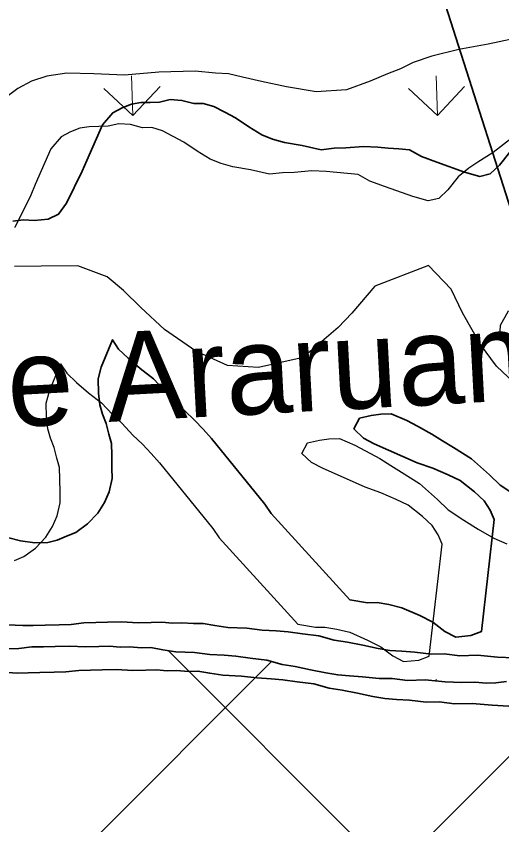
# Model space of a CAD drawing. Extents: x -10.5 to 30.8, y 18.4 to 58.7.
# Drawn here: x 1.997 to 3.031, y 33.091 to 34.811 of the extents above; entities that cross this region are included whole.
import ezdxf

# ---------------------------------------------------------------- set-up
doc = ezdxf.new("R2010")
doc.units = 0
doc.header["$LTSCALE"] = 0.08
for name, color, linetype, lineweight in [('10', 7, 'Continuous', 35), ('11', 7, 'Continuous', 13), ('18', 7, 'Continuous', 25), ('21', 7, 'Continuous', 25), ('43', 7, 'Continuous', 13), ('47', 7, 'Continuous', 25), ('48', 7, 'Continuous', 35), ('50', 7, 'Continuous', 25), ('51', 7, 'Continuous', 35), ('9', 7, 'Continuous', 25)]:
    doc.layers.add(name, color=color, linetype=linetype, lineweight=lineweight)

msp = doc.modelspace()

# ---------------------------------------------------------------- linework, layer by layer
at = {"layer": '10'}
for points in [[(2.9101, 33.39517), (2.86736, 33.39914), (2.82976, 33.39824), (2.79705, 33.40247), (2.76947, 33.4018), (2.73425, 33.40597), (2.70662, 33.4078), (2.68149, 33.4097), (2.6563, 33.41411), (2.62353, 33.42083), (2.59077, 33.42755), (2.56307, 33.43189), (2.53025, 33.44112), (2.49503, 33.44528), (2.46482, 33.44956), (2.43969, 33.45146), (2.40956, 33.45324), (2.37684, 33.45746), (2.33667, 33.459), (2.30898, 33.46335), (2.28379, 33.46775), (2.26372, 33.46727), (2.23859, 33.46916), (2.21854, 33.46869), (2.19592, 33.47064), (2.17335, 33.4701), (2.14578, 33.46944), (2.11062, 33.4711), (2.08054, 33.47038), (2.05546, 33.46978), (2.03039, 33.46918), (2.00286, 33.46602), (1.97779, 33.46541)], [(3.04054, 33.39579), (3.01803, 33.39275), (2.99797, 33.39227), (2.97284, 33.39417), (2.94527, 33.39351), (2.9101, 33.39517)]]:
    msp.add_lwpolyline(points, dxfattribs=at)
at = {"layer": '11'}
msp.add_lwpolyline([(1.99392, 34.27854), (2.05029, 34.27957), (2.12812, 34.27988), (2.19108, 34.25681), (2.22558, 34.22765), (2.2623, 34.19109), (2.31268, 34.14481), (2.37966, 34.09819), (2.44718, 34.06804), (2.51297, 34.0639), (2.60779, 34.08497), (2.6826, 34.14912), (2.7117, 34.17907), (2.76039, 34.23687), (2.87477, 34.28096), (2.92274, 34.2301), (2.94717, 34.17973), (2.98527, 34.11266), (3.01942, 34.06686), (3.10428, 33.98663)], dxfattribs=at)
at = {"layer": '18'}
msp.add_lwpolyline([(3.10428, 33.98663), (3.01942, 34.06686), (2.98527, 34.11266), (2.94717, 34.17973), (2.92274, 34.2301), (2.87477, 34.28096), (2.76039, 34.23687), (2.7117, 34.17907), (2.6826, 34.14912), (2.60779, 34.08497), (2.51297, 34.0639), (2.44718, 34.06804), (2.37966, 34.09819), (2.31268, 34.14481), (2.2623, 34.19109), (2.22558, 34.22765), (2.19108, 34.25681), (2.12812, 34.27988), (2.05029, 34.27957), (1.99392, 34.27854)], dxfattribs=at)
at = {"layer": '21'}
for p, q in [((3.73639, 32.04564), (2.32048, 33.46154)), ((0.73047, 31.62819), (2.54052, 33.43823)), ((1.49157, 31.68218), (3.22205, 33.41266))]:
    msp.add_line(p, q, dxfattribs=at)
for points in [[(2.9101, 33.39517), (2.86736, 33.39914), (2.82976, 33.39824), (2.79705, 33.40247), (2.76947, 33.4018), (2.73425, 33.40597), (2.70662, 33.4078), (2.68149, 33.4097), (2.6563, 33.41411), (2.62353, 33.42083), (2.59077, 33.42755), (2.56307, 33.43189), (2.53025, 33.44112), (2.49503, 33.44528), (2.46482, 33.44956), (2.43969, 33.45146), (2.40956, 33.45324), (2.37684, 33.45746), (2.33667, 33.459), (2.30898, 33.46335), (2.28379, 33.46775), (2.26372, 33.46727), (2.23859, 33.46916), (2.21854, 33.46869), (2.19592, 33.47064), (2.17335, 33.4701), (2.14578, 33.46944), (2.11062, 33.4711), (2.08054, 33.47038), (2.05546, 33.46978), (2.03039, 33.46918), (2.00286, 33.46602), (1.97779, 33.46541)], [(3.04054, 33.39579), (3.01803, 33.39275), (2.99797, 33.39227), (2.97284, 33.39417), (2.94527, 33.39351), (2.9101, 33.39517)]]:
    msp.add_lwpolyline(points, dxfattribs=at)
at = {"layer": '43'}
for p, q in [((2.24562, 34.59965), (2.24282, 34.68398)), ((2.24562, 34.59965), (2.24282, 34.68398)), ((2.89348, 34.59965), (2.89067, 34.68398)), ((2.89348, 34.59965), (2.89067, 34.68398)), ((2.24562, 34.59965), (2.18401, 34.6573)), ((2.24562, 34.59965), (2.18401, 34.6573)), ((2.24562, 34.59965), (2.30327, 34.66127)), ((2.24562, 34.59965), (2.30327, 34.66127)), ((2.89348, 34.59965), (2.83186, 34.6573)), ((2.89348, 34.59965), (2.83186, 34.6573)), ((2.89348, 34.59965), (2.95112, 34.66127)), ((2.89348, 34.59965), (2.95112, 34.66127)), ((2.89079, 33.39696), (2.89067, 33.40042)), ((2.89079, 33.39696), (2.89067, 33.40042))]:
    msp.add_line(p, q, dxfattribs=at)
for points in [[(3.05641, 34.55508), (3.01203, 34.52148), (2.97989, 34.50068), (2.96013, 34.48769), (2.93796, 34.46964), (2.91604, 34.44158), (2.89638, 34.42359), (2.87394, 34.41804), (2.84111, 34.42727), (2.78292, 34.4484), (2.75003, 34.46012), (2.72462, 34.47454), (2.702, 34.47649), (2.67937, 34.47846), (2.65676, 34.48042), (2.62661, 34.4822), (2.58906, 34.47879), (2.56399, 34.47819), (2.53647, 34.47503), (2.49612, 34.48407), (2.45834, 34.49067), (2.43309, 34.49758), (2.41029, 34.50704), (2.38232, 34.5239), (2.35427, 34.54324), (2.33142, 34.55521), (2.30857, 34.56718), (2.28583, 34.57414), (2.26577, 34.57366), (2.24053, 34.58057), (2.2154, 34.58247), (2.19294, 34.57692), (2.17289, 34.57644), (2.15283, 34.57596), (2.13283, 34.57298), (2.11294, 34.56499), (2.09312, 34.5545), (2.07113, 34.52895), (2.03776, 34.45305), (2.02825, 34.4303), (1.99471, 34.36191)], [(3.05641, 34.55508), (3.01203, 34.52148), (2.97989, 34.50068), (2.96013, 34.48769), (2.93796, 34.46964), (2.91604, 34.44158), (2.89638, 34.42359), (2.87394, 34.41804), (2.84111, 34.42727), (2.78292, 34.4484), (2.75003, 34.46012), (2.72462, 34.47454), (2.702, 34.47649), (2.67937, 34.47846), (2.65676, 34.48042), (2.62661, 34.4822), (2.58906, 34.47879), (2.56399, 34.47819), (2.53647, 34.47503), (2.49612, 34.48407), (2.45834, 34.49067), (2.43309, 34.49758), (2.41029, 34.50704), (2.38232, 34.5239), (2.35427, 34.54324), (2.33142, 34.55521), (2.30857, 34.56718), (2.28583, 34.57414), (2.26577, 34.57366), (2.24053, 34.58057), (2.2154, 34.58247), (2.19294, 34.57692), (2.17289, 34.57644), (2.15283, 34.57596), (2.13283, 34.57298), (2.11294, 34.56499), (2.09312, 34.5545), (2.07113, 34.52895), (2.03776, 34.45305), (2.02825, 34.4303), (1.99471, 34.36191)], [(3.04623, 34.12682), (3.02617, 34.12634), (3.02805, 34.15391), (3.0449, 34.18435)], [(3.04623, 34.12682), (3.02617, 34.12634), (3.02805, 34.15391), (3.0449, 34.18435)], [(1.99351, 33.65352), (2.0134, 33.6615), (2.03807, 33.67962), (2.06011, 33.70267), (2.07464, 33.72555), (2.08414, 33.7483), (2.09103, 33.77601), (2.09052, 33.79852), (2.08987, 33.82604), (2.0893, 33.85106), (2.08383, 33.87095), (2.07828, 33.89334), (2.07031, 33.91318), (2.06483, 33.93307), (2.06174, 33.95803), (2.06104, 33.98805), (2.06799, 34.01324), (2.09173, 34.07138), (2.10473, 34.05167), (2.12525, 34.03214), (2.15084, 34.01022), (2.17894, 33.98837), (2.20208, 33.96389), (2.2226, 33.94436), (2.24576, 33.91989), (2.26627, 33.90036), (2.28428, 33.88076), (2.30229, 33.86117), (2.4159, 33.72122), (2.4289, 33.70151), (2.5962, 33.51779), (2.63398, 33.51119), (2.65404, 33.51167), (2.67923, 33.50727), (2.70699, 33.50043), (2.745, 33.48382), (2.77293, 33.46947), (2.79846, 33.45006), (2.82132, 33.43809), (2.85385, 33.44137), (2.87624, 33.44942), (2.90334, 33.68786), (2.89536, 33.70769), (2.88236, 33.72741), (2.86184, 33.74694), (2.83118, 33.77123), (2.80582, 33.78314), (2.77287, 33.79737), (2.73999, 33.80909), (2.64875, 33.84946), (2.6259, 33.86142), (2.60538, 33.88096), (2.61739, 33.90377), (2.64235, 33.90938), (2.66235, 33.91236), (2.68492, 33.9129), (2.71785, 33.89867), (2.74071, 33.8867), (2.7712, 33.86992), (2.79411, 33.85545), (2.81703, 33.84098), (2.85521, 33.81686), (2.89362, 33.78274), (2.91671, 33.76077), (2.94983, 33.73903), (2.98037, 33.71974), (3.01344, 33.70051), (3.0413, 33.68866)], [(1.99351, 33.65352), (2.0134, 33.6615), (2.03807, 33.67962), (2.06011, 33.70267), (2.07464, 33.72555), (2.08414, 33.7483), (2.09103, 33.77601), (2.09052, 33.79852), (2.08987, 33.82604), (2.0893, 33.85106), (2.08383, 33.87095), (2.07828, 33.89334), (2.07031, 33.91318), (2.06483, 33.93307), (2.06174, 33.95803), (2.06104, 33.98805), (2.06799, 34.01324), (2.09173, 34.07138), (2.10473, 34.05167), (2.12525, 34.03214), (2.15084, 34.01022), (2.17894, 33.98837), (2.20208, 33.96389), (2.2226, 33.94436), (2.24576, 33.91989), (2.26627, 33.90036), (2.28428, 33.88076), (2.30229, 33.86117), (2.4159, 33.72122), (2.4289, 33.70151), (2.5962, 33.51779), (2.63398, 33.51119), (2.65404, 33.51167), (2.67923, 33.50727), (2.70699, 33.50043), (2.745, 33.48382), (2.77293, 33.46947), (2.79846, 33.45006), (2.82132, 33.43809), (2.85385, 33.44137), (2.87624, 33.44942), (2.90334, 33.68786), (2.89536, 33.70769), (2.88236, 33.72741), (2.86184, 33.74694), (2.83118, 33.77123), (2.80582, 33.78314), (2.77287, 33.79737), (2.73999, 33.80909), (2.64875, 33.84946), (2.6259, 33.86142), (2.60538, 33.88096), (2.61739, 33.90377), (2.64235, 33.90938), (2.66235, 33.91236), (2.68492, 33.9129), (2.71785, 33.89867), (2.74071, 33.8867), (2.7712, 33.86992), (2.79411, 33.85545), (2.81703, 33.84098), (2.85521, 33.81686), (2.89362, 33.78274), (2.91671, 33.76077), (2.94983, 33.73903), (2.98037, 33.71974), (3.01344, 33.70051), (3.0413, 33.68866)], [(1.97779, 33.46541), (2.00286, 33.46602), (2.03039, 33.46918), (2.05546, 33.46978), (2.08054, 33.47038), (2.11062, 33.4711), (2.14578, 33.46944), (2.17335, 33.4701), (2.19592, 33.47064), (2.21854, 33.46869), (2.23859, 33.46916), (2.26372, 33.46727), (2.28379, 33.46775), (2.30898, 33.46335), (2.33667, 33.459), (2.37684, 33.45746), (2.40956, 33.45324), (2.43969, 33.45146), (2.46482, 33.44956), (2.49503, 33.44528), (2.53025, 33.44112), (2.56307, 33.43189), (2.59077, 33.42755), (2.62353, 33.42083), (2.6563, 33.41411), (2.68149, 33.4097), (2.70662, 33.4078), (2.73425, 33.40597), (2.76947, 33.4018), (2.79705, 33.40247), (2.82976, 33.39824), (2.86736, 33.39914), (2.9101, 33.39517)], [(1.97779, 33.46541), (2.00286, 33.46602), (2.03039, 33.46918), (2.05546, 33.46978), (2.08054, 33.47038), (2.11062, 33.4711), (2.14578, 33.46944), (2.17335, 33.4701), (2.19592, 33.47064), (2.21854, 33.46869), (2.23859, 33.46916), (2.26372, 33.46727), (2.28379, 33.46775), (2.30898, 33.46335), (2.33667, 33.459), (2.37684, 33.45746), (2.40956, 33.45324), (2.43969, 33.45146), (2.46482, 33.44956), (2.49503, 33.44528), (2.53025, 33.44112), (2.56307, 33.43189), (2.59077, 33.42755), (2.62353, 33.42083), (2.6563, 33.41411), (2.68149, 33.4097), (2.70662, 33.4078), (2.73425, 33.40597), (2.76947, 33.4018), (2.79705, 33.40247), (2.82976, 33.39824), (2.86736, 33.39914), (2.9101, 33.39517)], [(2.9101, 33.39517), (2.94527, 33.39351), (2.97284, 33.39417), (2.99797, 33.39227), (3.01803, 33.39275), (3.04054, 33.39579)], [(2.9101, 33.39517), (2.94527, 33.39351), (2.97284, 33.39417), (2.99797, 33.39227), (3.01803, 33.39275), (3.04054, 33.39579)]]:
    msp.add_lwpolyline(points, dxfattribs=at)
at = {"layer": '48'}
for points in [[(1.99008, 34.37516), (2.01258, 34.37823), (2.03521, 34.3763), (2.06523, 34.37957), (2.08755, 34.39015), (2.10454, 34.41311), (2.13799, 34.48154), (2.14747, 34.50431), (2.18073, 34.58025), (2.20269, 34.60583), (2.22249, 34.61635), (2.24237, 34.62436), (2.26237, 34.62737), (2.28243, 34.62788), (2.30248, 34.62839), (2.32493, 34.63396), (2.35006, 34.6321), (2.37531, 34.62523), (2.39537, 34.62574), (2.41812, 34.61881), (2.44099, 34.60687), (2.46385, 34.59493), (2.49193, 34.57562), (2.51993, 34.55881), (2.54274, 34.54938), (2.568, 34.54251), (2.60579, 34.53595), (2.64614, 34.52697), (2.67366, 34.53017), (2.69873, 34.5308), (2.73627, 34.53426), (2.76643, 34.53252), (2.78904, 34.53059), (2.81167, 34.52866), (2.8343, 34.52673), (2.85973, 34.51236), (2.89263, 34.50068), (2.95086, 34.47963), (2.98369, 34.47045), (3.00613, 34.47602), (3.02576, 34.49404), (3.04764, 34.52213)], [(3.06052, 33.79154), (3.02737, 33.81323), (3.00425, 33.83517), (2.96579, 33.86924), (2.92757, 33.8933), (2.90463, 33.90774), (2.88171, 33.92218), (2.85119, 33.93892), (2.82832, 33.95086), (2.79537, 33.96504), (2.7728, 33.96447), (2.7528, 33.96146), (2.72785, 33.95582), (2.71587, 33.93299), (2.73642, 33.91349), (2.75928, 33.90155), (2.85058, 33.86131), (2.88348, 33.84963), (2.91644, 33.83545), (2.94182, 33.82357), (2.97251, 33.79932), (2.99307, 33.77982), (3.00609, 33.76012), (3.0141, 33.7403), (2.98733, 33.50183), (2.96494, 33.49375), (2.93242, 33.49042), (2.90954, 33.50235), (2.88398, 33.52173), (2.85604, 33.53604), (2.818, 33.5526), (2.79024, 33.55941), (2.76504, 33.56377), (2.74498, 33.56326), (2.70719, 33.56981), (2.53964, 33.7533), (2.52661, 33.77299), (2.41281, 33.91278), (2.39477, 33.93236), (2.37674, 33.95192), (2.35619, 33.97143), (2.33301, 33.99587), (2.31246, 34.01537), (2.28928, 34.03982), (2.26116, 34.06163), (2.23553, 34.08351), (2.21499, 34.10302), (2.20196, 34.12271), (2.1783, 34.06454), (2.17139, 34.03933), (2.17213, 34.00931), (2.17525, 33.98436), (2.18076, 33.96448), (2.18876, 33.94465), (2.19433, 33.92227), (2.19983, 33.90238), (2.20044, 33.87736), (2.20112, 33.84985), (2.20167, 33.82733), (2.19482, 33.79962), (2.18535, 33.77686), (2.17085, 33.75396), (2.14884, 33.73087), (2.1242, 33.71273), (2.10432, 33.70471), (2.08445, 33.6967), (2.06452, 33.69119), (2.03693, 33.69049), (2.00673, 33.69473), (1.98147, 33.7016)], [(1.97848, 33.51629), (2.01114, 33.51462), (2.0337, 33.51519), (2.05878, 33.51582), (2.08886, 33.51659), (2.11393, 33.51722), (2.14145, 33.52042), (2.16652, 33.52106), (2.19159, 33.5217), (2.22168, 33.52246), (2.25684, 33.52085), (2.28441, 33.52155), (2.30698, 33.52212), (2.32961, 33.52019), (2.34966, 33.5207), (2.37479, 33.51883), (2.39485, 33.51934), (2.42004, 33.51498), (2.44775, 33.51067), (2.48792, 33.50919), (2.52064, 33.50501), (2.55078, 33.50327), (2.57591, 33.50141), (2.60612, 33.49717), (2.64134, 33.49305), (2.67419, 33.48387), (2.70188, 33.47957), (2.73466, 33.47289), (2.76743, 33.46621), (2.79263, 33.46185), (2.81776, 33.45998), (2.84541, 33.45818), (2.88062, 33.45406), (2.9082, 33.45476), (2.94092, 33.45059), (2.97852, 33.45154), (3.02127, 33.44762), (3.05643, 33.44601)], [(3.05643, 33.44601), (3.02127, 33.44762), (2.97852, 33.45154), (2.94092, 33.45059), (2.9082, 33.45476), (2.88062, 33.45406), (2.84541, 33.45818), (2.81776, 33.45998), (2.79263, 33.46185), (2.76743, 33.46621), (2.73466, 33.47289), (2.70188, 33.47957), (2.67419, 33.48387), (2.64134, 33.49305), (2.60612, 33.49717), (2.57591, 33.50141), (2.55078, 33.50327), (2.52064, 33.50501), (2.48792, 33.50919), (2.44775, 33.51067), (2.42004, 33.51498), (2.39485, 33.51934), (2.37479, 33.51883), (2.34966, 33.5207), (2.32961, 33.52019), (2.30698, 33.52212), (2.28441, 33.52155), (2.25684, 33.52085), (2.22168, 33.52246), (2.19159, 33.5217), (2.16652, 33.52106), (2.14145, 33.52042), (2.11393, 33.51722), (2.08886, 33.51659), (2.05878, 33.51582), (2.0337, 33.51519), (2.01114, 33.51462), (1.97848, 33.51629)], [(1.96742, 33.41527), (2.00007, 33.41355), (2.02264, 33.41409), (2.04771, 33.41469), (2.07779, 33.41541), (2.10286, 33.41602), (2.13039, 33.41918), (2.15546, 33.41978), (2.18054, 33.42038), (2.21062, 33.4211), (2.24578, 33.41944), (2.27335, 33.4201), (2.29592, 33.42064), (2.31854, 33.41869), (2.33859, 33.41916), (2.36372, 33.41727), (2.38379, 33.41775), (2.40898, 33.41335), (2.43667, 33.409), (2.47684, 33.40746), (2.50956, 33.40324), (2.53969, 33.40146), (2.56482, 33.39956), (2.59503, 33.39528)], [(2.59503, 33.39528), (2.63025, 33.39112), (2.66307, 33.38189), (2.69077, 33.37755), (2.72353, 33.37083), (2.7563, 33.36411), (2.78149, 33.3597), (2.80662, 33.3578), (2.83425, 33.35596), (2.86947, 33.3518), (2.89705, 33.35247), (2.92976, 33.34824), (2.96736, 33.34914), (3.0101, 33.34517)], [(3.0101, 33.34517), (3.04527, 33.34351)]]:
    msp.add_lwpolyline(points, dxfattribs=at)
at = {"layer": '50'}
for points in [[(3.05641, 34.55508), (3.01203, 34.52148), (2.97989, 34.50068), (2.96013, 34.48769), (2.93796, 34.46964), (2.91604, 34.44158), (2.89638, 34.42359), (2.87394, 34.41804), (2.84111, 34.42727), (2.78292, 34.4484), (2.75003, 34.46012), (2.72462, 34.47454), (2.702, 34.47649), (2.67937, 34.47846), (2.65676, 34.48042), (2.62661, 34.4822), (2.58906, 34.47879), (2.56399, 34.47819), (2.53647, 34.47503), (2.49612, 34.48407), (2.45834, 34.49067), (2.43309, 34.49758), (2.41029, 34.50704), (2.38232, 34.5239), (2.35427, 34.54324), (2.33142, 34.55521), (2.30857, 34.56718), (2.28583, 34.57414), (2.26577, 34.57366), (2.24053, 34.58057), (2.2154, 34.58247), (2.19294, 34.57692), (2.17289, 34.57644), (2.15283, 34.57596), (2.13283, 34.57298), (2.11294, 34.56499), (2.09312, 34.5545), (2.07113, 34.52895), (2.03776, 34.45305), (2.02825, 34.4303), (1.99471, 34.36191)], [(3.04623, 34.12682), (3.02617, 34.12634), (3.02805, 34.15391), (3.0449, 34.18435)], [(1.99351, 33.65352), (2.0134, 33.6615), (2.03807, 33.67962), (2.06011, 33.70267), (2.07464, 33.72555), (2.08414, 33.7483), (2.09103, 33.77601), (2.09052, 33.79852), (2.08987, 33.82604), (2.0893, 33.85106), (2.08383, 33.87095), (2.07828, 33.89334), (2.07031, 33.91318), (2.06483, 33.93307), (2.06174, 33.95803), (2.06104, 33.98805), (2.06799, 34.01324), (2.09173, 34.07138), (2.10473, 34.05167), (2.12525, 34.03214), (2.15084, 34.01022), (2.17894, 33.98837), (2.20208, 33.96389), (2.2226, 33.94436), (2.24576, 33.91989), (2.26627, 33.90036), (2.28428, 33.88076), (2.30229, 33.86117), (2.4159, 33.72122), (2.4289, 33.70151), (2.5962, 33.51779), (2.63398, 33.51119), (2.65404, 33.51167), (2.67923, 33.50727), (2.70699, 33.50043), (2.745, 33.48382), (2.77293, 33.46947), (2.79846, 33.45006), (2.82132, 33.43809), (2.85385, 33.44137), (2.87624, 33.44942), (2.90334, 33.68786), (2.89536, 33.70769), (2.88236, 33.72741), (2.86184, 33.74694), (2.83118, 33.77123), (2.80582, 33.78314), (2.77287, 33.79737), (2.73999, 33.80909), (2.64875, 33.84946), (2.6259, 33.86142), (2.60538, 33.88096), (2.61739, 33.90377), (2.64235, 33.90938), (2.66235, 33.91236), (2.68492, 33.9129), (2.71785, 33.89867), (2.74071, 33.8867), (2.7712, 33.86992), (2.79411, 33.85545), (2.81703, 33.84098), (2.85521, 33.81686), (2.89362, 33.78274), (2.91671, 33.76077), (2.94983, 33.73903), (2.98037, 33.71974), (3.01344, 33.70051), (3.0413, 33.68866)]]:
    msp.add_lwpolyline(points, dxfattribs=at)
at = {"layer": '51'}
msp.add_line((0.23174, 43.22066), (3.42713, 33.21789), dxfattribs=at)
at = {"layer": '9'}
msp.add_lwpolyline([(3.08158, 34.76844), (3.00169, 34.75151), (2.93925, 34.74), (2.88187, 34.72611), (2.84205, 34.71264), (2.81476, 34.69947), (2.7874, 34.6888), (2.75014, 34.67289), (2.7004, 34.65417), (2.63528, 34.65011), (2.57231, 34.66111), (2.51936, 34.67236), (2.47902, 34.6814), (2.44876, 34.68819), (2.42113, 34.69003), (2.37839, 34.69401), (2.30065, 34.69214), (2.22807, 34.6854), (2.16276, 34.68883), (2.10504, 34.68996), (2.06253, 34.68393), (2.03017, 34.67314), (2.00043, 34.65741), (1.96345, 34.62899)], dxfattribs=at)

# ---------------------------------------------------------------- texts
at = {"layer": '47'}
msp.add_text(' Lagoa de Araruama', height=0.1896, rotation=3.042, dxfattribs=at).set_placement((0.997, 33.88432))

doc.saveas('drawing.dxf')
